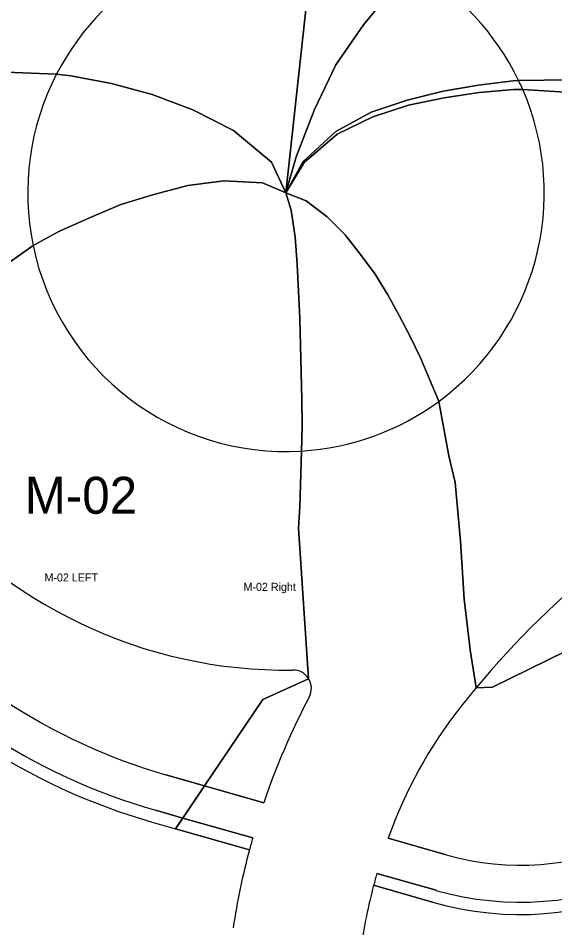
# Model space of a CAD drawing. Extents: x 5196716 to 5200291, y 3709146 to 3713154.
# Drawn here: x 5197407.8 to 5197495, y 3709224.3 to 3709372.1 of the extents above; entities that cross this region are included whole.
import ezdxf

# ---------------------------------------------------------------- set-up
doc = ezdxf.new("R2010")
doc.units = 0
for name, color, linetype in [('dsnTextNote', 7, 'Continuous'), ('Level 1', 7, 'Continuous'), ('Level 2', 7, 'Continuous'), ('Level 4', 7, 'Continuous')]:
    doc.layers.add(name, color=color, linetype=linetype)

msp = doc.modelspace()

# ---------------------------------------------------------------- linework, layer by layer
at = {"layer": 'Level 1'}
for p, q in [((5197451.32, 3709343.7), (5197455.86, 3709385.45)), ((5197455.86, 3709385.45), (5197451.32, 3709343.7)), ((5197459.45, 3709364.51), (5197463.95, 3709371)), ((5197463.95, 3709371), (5197459.45, 3709364.51)), ((5197455.96, 3709357.22), (5197459.45, 3709364.51)), ((5197459.45, 3709364.51), (5197455.96, 3709357.22)), ((5197414.02, 3709363.01), (5197401.27, 3709363.5)), ((5197401.27, 3709363.5), (5197414.02, 3709363.01)), ((5197416.35, 3709362.72), (5197414.02, 3709363.01)), ((5197414.02, 3709363.01), (5197416.35, 3709362.72)), ((5197422.93, 3709361.46), (5197416.35, 3709362.72)), ((5197416.35, 3709362.72), (5197422.93, 3709361.46)), ((5197429.56, 3709359.66), (5197422.93, 3709361.46)), ((5197422.93, 3709361.46), (5197429.56, 3709359.66)), ((5197489.15, 3709361.95), (5197488.28, 3709361.88)), ((5197436.2, 3709357.2), (5197429.56, 3709359.66)), ((5197429.56, 3709359.66), (5197436.2, 3709357.2)), ((5197471.26, 3709357.93), (5197477.04, 3709359.15)), ((5197477.04, 3709359.15), (5197471.26, 3709357.93)), ((5197471.26, 3709357.93), (5197477.04, 3709359.15)), ((5197488.39, 3709360.47), (5197489.82, 3709360.49)), ((5197489.82, 3709360.49), (5197488.39, 3709360.47)), ((5197488.39, 3709360.47), (5197489.82, 3709360.49)), ((5197489.82, 3709360.49), (5197503.44, 3709359.62)), ((5197503.44, 3709359.62), (5197489.82, 3709360.49)), ((5197489.82, 3709360.49), (5197503.44, 3709359.62)), ((5197465.42, 3709356.08), (5197471.26, 3709357.93)), ((5197442.81, 3709353.86), (5197436.2, 3709357.2)), ((5197459.63, 3709353.24), (5197465.42, 3709356.08)), ((5197448.96, 3709348.68), (5197442.81, 3709353.86)), ((5197454.28, 3709348.61), (5197459.63, 3709353.24)), ((5197459.63, 3709353.24), (5197454.28, 3709348.61)), ((5197454.28, 3709348.61), (5197459.63, 3709353.24)), ((5197454.1, 3709348.8), (5197451.32, 3709343.7)), ((5197451.32, 3709343.7), (5197448.96, 3709348.68)), ((5197448.96, 3709348.68), (5197451.32, 3709343.7)), ((5197451.32, 3709343.7), (5197454.28, 3709348.61)), ((5197454.28, 3709348.61), (5197451.32, 3709343.7)), ((5197451.32, 3709343.7), (5197454.28, 3709348.61)), ((5197429.82, 3709343.46), (5197435.38, 3709344.89)), ((5197435.38, 3709344.89), (5197441.24, 3709345.68)), ((5197441.24, 3709345.68), (5197447.48, 3709345.33)), ((5197447.48, 3709345.33), (5197451.32, 3709343.7)), ((5197424.45, 3709341.79), (5197429.82, 3709343.46)), ((5197403.22, 3709330.19), (5197410.2, 3709335.15)), ((5197410.2, 3709335.15), (5197403.22, 3709330.19)), ((5197453.56, 3709323.32), (5197453.35, 3709327.71)), ((5197476.17, 3709309.84), (5197476.17, 3709309.84)), ((5197476.17, 3709309.84), (5197477.81, 3709300.98)), ((5197453.57, 3709292.73), (5197453.86, 3709301.78)), ((5197453.57, 3709292.73), (5197453.86, 3709301.78)), ((5197477.81, 3709300.98), (5197478.82, 3709296.65)), ((5197478.82, 3709296.65), (5197479.69, 3709287.14)), ((5197453.36, 3709289.24), (5197453.57, 3709292.73)), ((5197453.36, 3709289.24), (5197453.57, 3709292.73)), ((5197455.01, 3709264.77), (5197453.36, 3709289.24)), ((5197455.01, 3709264.77), (5197453.36, 3709289.24)), ((5197479.69, 3709287.14), (5197480.29, 3709277.7)), ((5197480.29, 3709277.7), (5197481.28, 3709269.51)), ((5197481.28, 3709269.51), (5197482.26, 3709263.34)), ((5197484.92, 3709263.43), (5197496.83, 3709269.25)), ((5197447.56, 3709261.41), (5197455.01, 3709264.77)), ((5197447.56, 3709261.41), (5197455.01, 3709264.77)), ((5197482.26, 3709263.34), (5197484.92, 3709263.43)), ((5197433.37, 3709240.43), (5197447.56, 3709261.41)), ((5197438.08, 3709247.4), (5197447.56, 3709261.41)), ((5197434.55, 3709242.17), (5197438.08, 3709247.4)), ((5197429.57, 3709241.51), (5197433.37, 3709240.43)), ((5197433.37, 3709240.43), (5197434.55, 3709242.17)), ((5197445.38, 3709237), (5197433.37, 3709240.43)), ((5197475.17, 3709228.51), (5197465.58, 3709231.24))]:
    msp.add_line(p, q, dxfattribs=at)
for points in [[(5197472.07, 3709380.22), (5197468.83, 3709376.97), (5197463.95, 3709371), (5197459.45, 3709364.51), (5197455.96, 3709357.22), (5197452.99, 3709349.55), (5197451.32, 3709343.7)], [(5197463.95, 3709371), (5197468.83, 3709376.97), (5197472.07, 3709380.22)], [(5197472.07, 3709380.22), (5197468.83, 3709376.97), (5197463.95, 3709371)], [(5197451.32, 3709343.7), (5197454.1, 3709348.8), (5197459.42, 3709353.67), (5197465.19, 3709356.79), (5197471.05, 3709358.78), (5197476.87, 3709360.2), (5197482.62, 3709361.2), (5197488.28, 3709361.88), (5197489.15, 3709361.95)], [(5197488.28, 3709361.88), (5197482.62, 3709361.2), (5197476.87, 3709360.2)], [(5197502.7, 3709361.87), (5197497.48, 3709362.04), (5197489.15, 3709361.95)], [(5197489.15, 3709361.95), (5197497.48, 3709362.04), (5197502.7, 3709361.87)], [(5197476.87, 3709360.2), (5197471.05, 3709358.78), (5197465.19, 3709356.79)], [(5197477.04, 3709359.15), (5197482.74, 3709360.01), (5197488.39, 3709360.47)], [(5197488.39, 3709360.47), (5197482.74, 3709360.01), (5197477.04, 3709359.15)], [(5197477.04, 3709359.15), (5197482.74, 3709360.01), (5197488.39, 3709360.47)], [(5197459.63, 3709353.24), (5197465.42, 3709356.08), (5197471.26, 3709357.93)], [(5197471.26, 3709357.93), (5197465.42, 3709356.08), (5197459.63, 3709353.24)], [(5197436.2, 3709357.2), (5197442.81, 3709353.86), (5197448.96, 3709348.68)], [(5197451.32, 3709343.7), (5197452.99, 3709349.55), (5197455.96, 3709357.22)], [(5197455.96, 3709357.22), (5197452.99, 3709349.55), (5197451.32, 3709343.7)], [(5197465.19, 3709356.79), (5197459.42, 3709353.67), (5197454.1, 3709348.8)], [(5197451.32, 3709343.7), (5197447.48, 3709345.33), (5197441.24, 3709345.68), (5197435.38, 3709344.89), (5197429.82, 3709343.46), (5197424.45, 3709341.79), (5197419.38, 3709339.66), (5197414.39, 3709337.42), (5197410.2, 3709335.15)], [(5197451.32, 3709343.7), (5197454.63, 3709342.4), (5197458.04, 3709339.82), (5197460.95, 3709336.88), (5197463.46, 3709333.72), (5197465.8, 3709330.5), (5197467.87, 3709327.17), (5197469.74, 3709323.78), (5197471.5, 3709320.36), (5197473.18, 3709316.93), (5197474.68, 3709313.46), (5197476.11, 3709309.98), (5197476.17, 3709309.84)], [(5197453.86, 3709301.78), (5197453.94, 3709305.75), (5197453.9, 3709310.16), (5197453.79, 3709314.54), (5197453.67, 3709318.93), (5197453.56, 3709323.32), (5197453.35, 3709327.71), (5197453.15, 3709332.11), (5197452.81, 3709336.51), (5197452.17, 3709340.91), (5197451.32, 3709343.7)], [(5197452.81, 3709336.51), (5197452.17, 3709340.91), (5197451.32, 3709343.7)], [(5197451.32, 3709343.7), (5197454.63, 3709342.4), (5197458.04, 3709339.82), (5197460.95, 3709336.88)], [(5197410.2, 3709335.15), (5197414.39, 3709337.42), (5197419.38, 3709339.66), (5197424.45, 3709341.79)], [(5197453.35, 3709327.71), (5197453.15, 3709332.11), (5197452.81, 3709336.51)], [(5197460.95, 3709336.88), (5197463.46, 3709333.72), (5197465.8, 3709330.5)], [(5197465.8, 3709330.5), (5197467.87, 3709327.17), (5197469.74, 3709323.78), (5197471.5, 3709320.36)], [(5197453.9, 3709310.16), (5197453.79, 3709314.54), (5197453.67, 3709318.93), (5197453.56, 3709323.32)], [(5197471.5, 3709320.36), (5197473.18, 3709316.93), (5197474.68, 3709313.46)], [(5197474.68, 3709313.46), (5197476.11, 3709309.98), (5197476.17, 3709309.84)], [(5197453.86, 3709301.78), (5197453.94, 3709305.75), (5197453.9, 3709310.16)], [(5197476.17, 3709309.84), (5197477.81, 3709300.98), (5197478.82, 3709296.65)], [(5197478.82, 3709296.65), (5197479.69, 3709287.14), (5197480.29, 3709277.7)], [(5197480.29, 3709277.7), (5197481.28, 3709269.51), (5197482.26, 3709263.34)], [(5197482.26, 3709263.34), (5197484.92, 3709263.43), (5197496.83, 3709269.25), (5197513.52, 3709272.03), (5197546.76, 3709277.31)]]:
    msp.add_lwpolyline(points, dxfattribs=at)
for centre, radius, start, end in [((5197457.55, 3709339.6), 102, 218.7641, 254.0813), ((5197489.43, 3709278.51), 52, 254.0813, 333.8823), ((5197559.87, 3709206.43), 118.5, 165.0484, 171.3063), ((5197559.87, 3709206.43), 97.5, 165.2567, 171.3063)]:
    msp.add_arc(centre, radius, start, end, dxfattribs=at)
at = {"layer": 'Level 2'}
for p, q in [((5197401.27, 3709363.5), (5197414.02, 3709363.01)), ((5197414.02, 3709363.01), (5197401.27, 3709363.5)), ((5197503.44, 3709359.62), (5197489.82, 3709360.49)), ((5197489.82, 3709360.49), (5197489.82, 3709360.49)), ((5197489.82, 3709360.49), (5197503.44, 3709359.62)), ((5197410.2, 3709335.15), (5197403.22, 3709330.19)), ((5197403.22, 3709330.19), (5197410.2, 3709335.15)), ((5197410.2, 3709335.15), (5197410.2, 3709335.15)), ((5197477.81, 3709300.98), (5197476.17, 3709309.84)), ((5197453.57, 3709292.73), (5197453.86, 3709301.78)), ((5197453.86, 3709301.78), (5197453.57, 3709292.73)), ((5197453.86, 3709301.78), (5197453.86, 3709301.78)), ((5197478.82, 3709296.65), (5197477.81, 3709300.98)), ((5197453.36, 3709289.24), (5197453.57, 3709292.73)), ((5197453.57, 3709292.73), (5197453.36, 3709289.24)), ((5197455.01, 3709264.77), (5197453.36, 3709289.24)), ((5197453.36, 3709289.24), (5197455.01, 3709264.77)), ((5197481.28, 3709269.51), (5197480.29, 3709277.7)), ((5197482.26, 3709263.34), (5197481.28, 3709269.51)), ((5197438.08, 3709247.4), (5197431.77, 3709249.2)), ((5197434.55, 3709242.17), (5197438.08, 3709247.4)), ((5197438.08, 3709247.4), (5197434.55, 3709242.17)), ((5197447.7, 3709244.66), (5197438.08, 3709247.4)), ((5197430.12, 3709243.43), (5197434.55, 3709242.17)), ((5197434.55, 3709242.17), (5197445.91, 3709238.93)), ((5197477.37, 3709236.2), (5197467.93, 3709238.89)), ((5197466.1, 3709233.17), (5197475.72, 3709230.43))]:
    msp.add_line(p, q, dxfattribs=at)
for points in [[(5197489.15, 3709361.95), (5197497.48, 3709362.04), (5197502.7, 3709361.87)], [(5197502.7, 3709361.87), (5197497.48, 3709362.04), (5197489.15, 3709361.95)], [(5197476.17, 3709309.84), (5197477.81, 3709300.98), (5197478.82, 3709296.65)], [(5197478.82, 3709296.65), (5197479.69, 3709287.14), (5197480.29, 3709277.7)], [(5197480.29, 3709277.7), (5197479.69, 3709287.14), (5197478.82, 3709296.65)], [(5197480.29, 3709277.7), (5197481.28, 3709269.51), (5197482.26, 3709263.34)]]:
    msp.add_lwpolyline(points, dxfattribs=at)
for centre, radius, start, end in [((5197451.32, 3709343.7), 42, 83.8009, 152.6258), ((5197451.32, 3709343.7), 42, 25.7605, 60.3941), ((5197451.32, 3709343.7), 42, 152.6258, 191.7512), ((5197451.32, 3709343.7), 42, 23.5604, 25.7605), ((5197451.32, 3709343.7), 42, 306.2654, 23.5602), ((5197451.32, 3709343.7), 42, 191.7512, 273.4584), ((5197451.32, 3709343.7), 42, 273.4586, 306.2654), ((5197597.49, 3709167.3), 150, 117.2834, 140.1911), ((5197451.32, 3709343.7), 77.5, 218.2119, 270.8019), ((5197457.55, 3709339.6), 94, 218.7641, 254.0813), ((5197457.55, 3709339.6), 100, 218.7641, 254.0813), ((5197452.45, 3709263.21), 3, 31.471, 90.8019), ((5197452.45, 3709263.21), 3, 332.14, 31.471), ((5197597.49, 3709167.3), 150, 140.1911, 141.7675), ((5197559.87, 3709206.43), 118.5, 152.14, 161.179), ((5197538.58, 3709213.72), 75, 141.7675, 160.3867), ((5197489.43, 3709278.51), 44, 254.0813, 333.8823), ((5197489.43, 3709278.51), 50, 254.0813, 333.8823), ((5197559.87, 3709206.43), 118.5, 164.0813, 165.0484), ((5197559.87, 3709206.43), 118.5, 165.0484, 171.3063), ((5197559.87, 3709206.43), 97.5, 164.0813, 165.2567), ((5197559.87, 3709206.43), 97.5, 165.2567, 171.3063)]:
    msp.add_arc(centre, radius, start, end, dxfattribs=at)
at = {"layer": 'Level 4'}
for p, q in [((5197455.86, 3709385.45), (5197451.32, 3709343.7)), ((5197451.32, 3709343.7), (5197455.86, 3709385.45)), ((5197463.95, 3709371), (5197459.45, 3709364.51)), ((5197459.45, 3709364.51), (5197463.95, 3709371)), ((5197459.45, 3709364.51), (5197455.96, 3709357.22)), ((5197455.96, 3709357.22), (5197459.45, 3709364.51)), ((5197416.35, 3709362.72), (5197414.02, 3709363.01)), ((5197414.02, 3709363.01), (5197416.35, 3709362.72)), ((5197422.93, 3709361.46), (5197416.35, 3709362.72)), ((5197416.35, 3709362.72), (5197422.93, 3709361.46)), ((5197489.15, 3709361.95), (5197488.28, 3709361.88)), ((5197477.04, 3709359.15), (5197471.26, 3709357.93)), ((5197471.26, 3709357.93), (5197477.04, 3709359.15)), ((5197489.82, 3709360.49), (5197488.39, 3709360.47)), ((5197488.39, 3709360.47), (5197489.82, 3709360.49)), ((5197465.42, 3709356.08), (5197471.26, 3709357.93)), ((5197442.81, 3709353.86), (5197436.2, 3709357.2)), ((5197436.2, 3709357.2), (5197442.81, 3709353.86)), ((5197459.63, 3709353.24), (5197465.42, 3709356.08)), ((5197448.96, 3709348.68), (5197442.81, 3709353.86)), ((5197442.81, 3709353.86), (5197448.96, 3709348.68)), ((5197459.63, 3709353.24), (5197454.28, 3709348.61)), ((5197454.28, 3709348.61), (5197459.63, 3709353.24)), ((5197454.1, 3709348.8), (5197451.32, 3709343.7)), ((5197451.32, 3709343.7), (5197448.96, 3709348.68)), ((5197448.96, 3709348.68), (5197451.32, 3709343.7)), ((5197454.28, 3709348.61), (5197451.32, 3709343.7)), ((5197451.32, 3709343.7), (5197454.28, 3709348.61)), ((5197435.38, 3709344.89), (5197441.24, 3709345.68)), ((5197441.24, 3709345.68), (5197447.48, 3709345.33)), ((5197447.48, 3709345.33), (5197451.32, 3709343.7)), ((5197454.63, 3709342.4), (5197451.32, 3709343.7)), ((5197451.32, 3709343.7), (5197452.17, 3709340.91)), ((5197419.38, 3709339.66), (5197424.45, 3709341.79)), ((5197452.17, 3709340.91), (5197452.81, 3709336.51)), ((5197414.39, 3709337.42), (5197419.38, 3709339.66)), ((5197410.2, 3709335.15), (5197414.39, 3709337.42)), ((5197463.46, 3709333.72), (5197460.95, 3709336.88)), ((5197465.8, 3709330.5), (5197463.46, 3709333.72)), ((5197467.87, 3709327.17), (5197465.8, 3709330.5)), ((5197453.35, 3709327.71), (5197453.56, 3709323.32)), ((5197469.74, 3709323.78), (5197467.87, 3709327.17)), ((5197453.79, 3709314.54), (5197453.9, 3709310.16)), ((5197476.11, 3709309.98), (5197474.68, 3709313.46)), ((5197476.17, 3709309.84), (5197476.11, 3709309.98)), ((5197447.56, 3709261.41), (5197455.01, 3709264.77)), ((5197455.01, 3709264.77), (5197447.56, 3709261.41)), ((5197484.92, 3709263.43), (5197482.26, 3709263.34)), ((5197438.08, 3709247.4), (5197447.56, 3709261.41)), ((5197447.56, 3709261.41), (5197438.08, 3709247.4)), ((5197431.77, 3709249.2), (5197438.08, 3709247.4)), ((5197438.08, 3709247.4), (5197447.7, 3709244.66)), ((5197434.55, 3709242.17), (5197430.12, 3709243.43)), ((5197429.57, 3709241.51), (5197433.37, 3709240.43)), ((5197433.37, 3709240.43), (5197434.55, 3709242.17)), ((5197434.55, 3709242.17), (5197433.37, 3709240.43)), ((5197445.91, 3709238.93), (5197434.55, 3709242.17)), ((5197433.37, 3709240.43), (5197445.38, 3709237)), ((5197467.93, 3709238.89), (5197477.37, 3709236.2)), ((5197475.72, 3709230.43), (5197466.1, 3709233.17)), ((5197465.58, 3709231.24), (5197475.17, 3709228.51))]:
    msp.add_line(p, q, dxfattribs=at)
for points in [[(5197472.07, 3709380.22), (5197468.83, 3709376.97), (5197463.95, 3709371)], [(5197463.95, 3709371), (5197468.83, 3709376.97), (5197472.07, 3709380.22)], [(5197436.2, 3709357.2), (5197429.56, 3709359.66), (5197422.93, 3709361.46)], [(5197422.93, 3709361.46), (5197429.56, 3709359.66), (5197436.2, 3709357.2)], [(5197451.32, 3709343.7), (5197454.1, 3709348.8), (5197459.42, 3709353.67), (5197465.19, 3709356.79), (5197471.05, 3709358.78), (5197476.87, 3709360.2), (5197482.62, 3709361.2), (5197488.28, 3709361.88), (5197489.15, 3709361.95)], [(5197488.28, 3709361.88), (5197482.62, 3709361.2), (5197476.87, 3709360.2)], [(5197476.87, 3709360.2), (5197471.05, 3709358.78), (5197465.19, 3709356.79)], [(5197488.39, 3709360.47), (5197482.74, 3709360.01), (5197477.04, 3709359.15)], [(5197477.04, 3709359.15), (5197482.74, 3709360.01), (5197488.39, 3709360.47)], [(5197489.82, 3709360.49), (5197489.82, 3709360.49)], [(5197471.26, 3709357.93), (5197465.42, 3709356.08), (5197459.63, 3709353.24)], [(5197455.96, 3709357.22), (5197452.99, 3709349.55), (5197451.32, 3709343.7)], [(5197451.32, 3709343.7), (5197452.99, 3709349.55), (5197455.96, 3709357.22)], [(5197465.19, 3709356.79), (5197459.42, 3709353.67), (5197454.1, 3709348.8)], [(5197451.32, 3709343.7), (5197447.48, 3709345.33), (5197441.24, 3709345.68), (5197435.38, 3709344.89), (5197429.82, 3709343.46), (5197424.45, 3709341.79), (5197419.38, 3709339.66), (5197414.39, 3709337.42), (5197410.2, 3709335.15)], [(5197424.45, 3709341.79), (5197429.82, 3709343.46), (5197435.38, 3709344.89)], [(5197453.86, 3709301.78), (5197453.94, 3709305.75), (5197453.9, 3709310.16), (5197453.79, 3709314.54), (5197453.67, 3709318.93), (5197453.56, 3709323.32), (5197453.35, 3709327.71), (5197453.15, 3709332.11), (5197452.81, 3709336.51), (5197452.17, 3709340.91), (5197451.32, 3709343.7)], [(5197451.32, 3709343.7), (5197454.63, 3709342.4), (5197458.04, 3709339.82), (5197460.95, 3709336.88), (5197463.46, 3709333.72), (5197465.8, 3709330.5), (5197467.87, 3709327.17), (5197469.74, 3709323.78), (5197471.5, 3709320.36), (5197473.18, 3709316.93), (5197474.68, 3709313.46), (5197476.11, 3709309.98), (5197476.17, 3709309.84)], [(5197460.95, 3709336.88), (5197458.04, 3709339.82), (5197454.63, 3709342.4)], [(5197452.81, 3709336.51), (5197453.15, 3709332.11), (5197453.35, 3709327.71)], [(5197474.68, 3709313.46), (5197473.18, 3709316.93), (5197471.5, 3709320.36), (5197469.74, 3709323.78)], [(5197453.56, 3709323.32), (5197453.67, 3709318.93), (5197453.79, 3709314.54)], [(5197453.9, 3709310.16), (5197453.94, 3709305.75), (5197453.86, 3709301.78)], [(5197482.26, 3709263.34), (5197484.92, 3709263.43), (5197496.83, 3709269.25), (5197513.52, 3709272.03), (5197537.1, 3709275.77)], [(5197513.52, 3709272.03), (5197496.83, 3709269.25), (5197484.92, 3709263.43)]]:
    msp.add_lwpolyline(points, dxfattribs=at)
for centre, radius, start, end in [((5197451.32, 3709343.7), 42, 83.8009, 152.6258), ((5197451.32, 3709343.7), 42, 25.7605, 60.3941), ((5197451.32, 3709343.7), 42, 152.6258, 191.7512), ((5197451.32, 3709343.7), 42, 23.5604, 25.7605), ((5197451.32, 3709343.7), 42, 306.2654, 23.5602), ((5197451.32, 3709343.7), 42, 191.7511, 273.4584), ((5197451.32, 3709343.7), 42, 273.4585, 306.2654), ((5197597.49, 3709167.3), 150, 117.2834, 140.1911), ((5197451.32, 3709343.7), 77.5, 218.2119, 270.8019), ((5197457.55, 3709339.6), 94, 218.7641, 254.0813), ((5197457.55, 3709339.6), 100, 218.7641, 254.0813), ((5197457.55, 3709339.6), 102, 218.7641, 254.0813), ((5197452.45, 3709263.21), 3, 31.471, 90.8019), ((5197452.45, 3709263.21), 3, 332.14, 31.471), ((5197597.49, 3709167.3), 150, 140.1911, 141.7675), ((5197559.87, 3709206.43), 118.5, 152.14, 161.179), ((5197538.58, 3709213.72), 75, 141.7675, 160.3867), ((5197489.43, 3709278.51), 44, 254.0813, 333.8823), ((5197489.43, 3709278.51), 50, 254.0813, 333.8823), ((5197489.43, 3709278.51), 52, 254.0813, 333.8823), ((5197559.87, 3709206.43), 118.5, 164.0813, 165.0484), ((5197559.87, 3709206.43), 97.5, 164.0813, 165.2567)]:
    msp.add_arc(centre, radius, start, end, dxfattribs=at)

# ---------------------------------------------------------------- texts
at = {"layer": 'dsnTextNote'}
for s, height, p in [('M-02', 6, (5197408.84, 3709291.59)), ('M-02 LEFT', 1.3, (5197412.06, 3709280.59)), ('M-02 Right', 1.3, (5197444.42, 3709279.07))]:
    msp.add_text(s, height=height, dxfattribs=at).set_placement(p)

doc.saveas('drawing.dxf')
